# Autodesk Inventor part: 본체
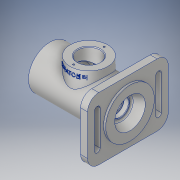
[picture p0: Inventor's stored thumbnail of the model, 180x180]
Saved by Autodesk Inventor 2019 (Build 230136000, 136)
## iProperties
Created: 2021-07
Part Number: 본체
Material: 알루미늄 6061
Document SubType Name: Modeling
Designer: jun-2-6
Mass: 729.943 g
Surface Area: 649.096 cm^2
Volume: 270.349 cm^3
Density: 2.7 g/cm^3
Appearance: 알루미늄 - 평지
Author: jun-2-6
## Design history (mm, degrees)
sketch "스케치1"
  geometry: L1 (-56, 20)-(-56, 31); L2 (-56, 31)-(-27, 31); L3 (27, 31)-(46, 31); L4 (59, 31)-(59, 22); L5 (-47, 20)-(-47, 24); L6 (-47, 24)-(-44, 24); L7 (-44, 24)-(-44, 20); L8 (-44, 20)-(-35, 20); L9 (-35, 20)-(-35, 17.5); L10 (-35, 17.5)-(-31.75, 17.5); L11 (-31.75, 17.5)-(-31.75, 18.5); L12 (-31.75, 18.5)-(-30, 18.5); L13 (-30, 18.5)-(-30, 17.5); L14 (-30, 17.5)-(-19, 17.5); L15 (-19, 17.5)-(-19, 26); L16 (-19, 26)-(19, 26); L17 (19, 26)-(19, 17.5); L18 (19, 17.5)-(30, 17.5); L19 (30, 17.5)-(30, 16); L20 (35, 10)-(37.7, 10); L21 (37.7, 10)-(37.7, 12.5); L22 (37.7, 12.5)-(44.3, 12.5); L23 (-79, 0)-(82, 0) reference; L24 (0, -7)-(0, 42) reference; L25 (45, 12.904)-(45, 16); L26 (45, 16)-(59, 22); L27 (44.3, 12.5)-(45, 12.904); L28 (-56, 20)-(-56, 0); L29 (-47, 0)-(-47, 20); L30 (30, 16)-(30, 16); L31 (30, 16)-(35, 16); L32 (35, 16)-(35, 10); L33 (-27, 31)-(27, 31); L34 (46, 31)-(56, 31); L35 (56, 31)-(56, 35); L36 (56, 35)-(59, 35); L37 (59, 35)-(59, 31); 1 further point
  constraints: 70 end point, 18 perpendicular, 11 point on line, 3 vertical, 2 horizontal, 1 collinear, 1 parallel
  dimensions: "d0" = 115 distance between parallel lines of L4 L1; "d2" = 56 distance between parallel lines of L1 L24; "d5" = 62 diameter of L2 L23; "d6" = 48 diameter of L6 L23; "d7" = 40 diameter of L8 L23; "d8" = 37 diameter of L12 L23; "d9" = 35 diameter of L14 L23; "d10" = 52 diameter of L16 L23; "d12" = 20 diameter of L20 L23; "d13" = 25 diameter of L22 L23; "d14" = 30 deg angle of L27 L22; "d15" = 32 diameter of L25.end L23; "d16" = 3 distance between parallel lines of L7 L5; "d17" = 9 distance between parallel lines of L9 L7; "d18" = 65 distance between parallel lines of L19 L9; "d19" = 9 distance between parallel lines of L1 L5; "d20" = 11 distance between parallel lines of L15 L13; "d23" = 38 distance between parallel lines of L17 L15; "d24" = 11 distance between parallel lines of L30 L17; "d25" = 1.75 distance between parallel lines of L13 L11; "d26" = 32 diameter of L31 L23; "d27" = 91 distance between parallel lines of L28 L32; "d28" = 14 distance between parallel lines of L4 L25; "d29" = 7.3 distance between parallel lines of L25 L21; "d30" = 0.7 distance from line of L25 L22.end; "d31" = 44 diameter of L4.end L23; "d86" = 70 diameter of L36 L23; "d87" = 3 distance between parallel lines of L37 L35
revolve "회전1" sketch "스케치1" stored, may be unused: angle "d32" = 90 deg
node "작업 평면1"
sketch "스케치2"
  geometry: L1 (-29, 58)-(29, 58); L2 (45, 42)-(45, -42); L3 (29, -58)-(-29, -58); L4 (-45, -42)-(-45, 42); L5 (-45, 58)-(45, -58); L6 (45, 58)-(-45, -58); C1 r 31 at (0, 0); A1 r 16 centre (29, 42) between (45, 42) and (29, 58); A2 r 16 centre (-29, 42) between (-29, 58) and (-45, 42); A3 r 16 centre (-29, -42) between (-45, -42) and (-29, -58); A4 r 16 centre (29, -42) between (29, -58) and (45, -42); 1 further point
  constraints: 12 end point, 8 point on circle, 8 point on line, 8 tangent, 5 centre point, 3 equal radius, 2 midpoint, 2 parallel, 1 coincident, 1 horizontal, 1 perpendicular
  dimensions: "d34" = 116 distance between parallel lines of L3 L1; "d35" = 90 distance between parallel lines of L4 L2; "d36" = 62 diameter of C1; "d51" = 16 radius of A1
extrude "돌출1" join sketch "스케치2" distance "d37" = 10; taper "d38" = 0 deg
sketch "스케치3"
  geometry: 2 further points
  constraints: 1 coincident
hole "구멍1" sketch "스케치3" at (0, 0) diameter "d39" = 40.376; stored, may be unused: countersink angle "d43" = 90 deg, drill point angle "d45" = 118 deg; dims "d40" = 9, "d41" = 4, "d42" = 2, "d44" = 9.3
sketch "스케치4"
  geometry: L1 (-44, 25)-(-44, -25); L2 (-48, 25)-(-48, -25); L3 (-40, -25)-(-40, 25); L4 (0, -63)-(0, 63) reference; L5 (81.2, 0)-(-81.2, 0) reference; L6 (40, -25)-(40, 25); L7 (48, 25)-(48, -25); A1 r 4 centre (-44, 25) between (-40, 25) and (-48, 25); A2 r 4 centre (-44, -25) between (-48, -25) and (-40, -25); A3 r 4 centre (44, 25) between (48, 25) and (40, 25); A4 r 4 centre (44, -25) between (40, -25) and (48, -25); 2 further points
  constraints: 12 end point, 8 point on circle, 6 symmetric about line, 4 centre point, 4 tangent, 1 midpoint, 1 parallel, 1 point on line, 1 vertical, 2 other
  dimensions: "d46" = 50 distance of L1.end L1.start; "d47" = 4 radius of A1; "d48" = 44 distance between parallel lines of L4 L1
extrude "돌출2" cut sketch "스케치4" distance "d49" = 10; taper "d50" = 0 deg
node "작업 평면2"
sketch "스케치5"
  geometry: L1 (37.8, 0)-(-37.8, 0) reference; L2 (0, -37.8)-(0, 37.8) reference; C1 r 27 at (0, 0); 1 further point
  constraints: 1 centre point, 1 coincident
  dimensions: "d53" = 54 diameter of C1
extrude "돌출3" join sketch "스케치5" stored distance "d54" = 10; taper "d55" = 0 deg
sketch "스케치6"
  geometry: 2 further points
  constraints: 1 coincident
hole "구멍2" sketch "스케치6" at (0, 0) diameter "d56" = 32; stored, may be unused: countersink angle "d60" = 90 deg, drill point angle "d62" = 118 deg; dims "d57" = 9, "d58" = 4, "d59" = 2, "d61" = 30
node "작업 평면3"
sketch "스케치7"
  geometry: L1 (-27, 42)-(27, 42) reference; L2 (0, -8.4)-(0, 50.4) reference; 2 further points
  constraints: 1 point on line, 1 other
  dimensions: "d64" = 8 distance from line of L1 point (0, 34)
feature "엠보싱1" sketch "스케치7" dims "d65" = 0.5, "d66" = 0
sketch "스케치8"
  geometry: A1 r 22 centre (0, 0) between (0, 22) and (0, -22); 1 further point
  constraints: 2 point on circle, 1 centre point, 1 coincident
  dimensions: "d67" = 44 diameter of A1
hole "구멍3" sketch "스케치8" at (0, 22), (0, -22) diameter "d68" = 2.459; stored, may be unused: countersink angle "d72" = 90 deg, drill point angle "d74" = 118 deg; dims "d69" = 6, "d70" = 4, "d71" = 2, "d73" = 8
fillet "모깎기1" dims "d75" = 3
fillet "모깎기2" dims "d76" = 3
chamfer "모따기1" distance "d77" = 1; stored, may be unused: second distance "d78" = 2, angle "d79" = 45 deg
fillet "모깎기3" dims "d80" = 3
fillet "모깎기4" dims "d81" = 0.3
fillet "모깎기5" dims "d82" = 3
chamfer "모따기2" distance "d83" = 1; stored, may be unused: second distance "d84" = 2, angle "d85" = 45 deg
node "솔리드1"
other parameters: "d33" = 46, "d52" = 42, "d63" = 27
